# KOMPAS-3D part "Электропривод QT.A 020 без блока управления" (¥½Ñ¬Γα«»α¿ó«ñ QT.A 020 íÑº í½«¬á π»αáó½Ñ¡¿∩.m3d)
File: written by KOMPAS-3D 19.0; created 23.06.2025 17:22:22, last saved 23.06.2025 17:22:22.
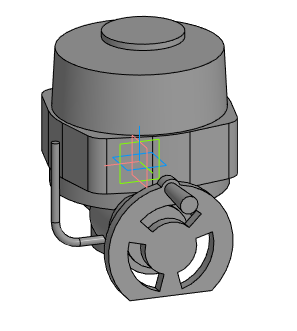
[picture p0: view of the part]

Document properties: Автор: Евгений; Полное имя файла: E:\Dendor Работа Сачек\3D для проектировщиков\3.5 Тип QT.А Электропривод\stp_Электропривод QT.A без блока управления\Электропривод QT.A 020 без блока управления.m3d

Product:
- Part/product: Электропривод QT.A 020 без блока управления

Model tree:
1. Операция без истории:1  (labels: Электропривод QT.A 020 без блока управления)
